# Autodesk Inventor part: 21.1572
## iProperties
Created: 2006-02
Part Number: 21.1572
Material: Steel, Mild
Description: M8 WASHER FOR LR6
Document SubType Name: Modeling
Standard: DIN 125
Designer: Andy Moles
Standards Organization: DIN
Language: en-US
Size Designation: A 8.4
Categories: <MemberInstance><Categories><Category DisplayName="Fasteners" InternalName="e4da775c-781d-43d5-af7c-5136215cf5a6" Mnemonic="FSTN"><Category DisplayName="Washers
Density: 7.86 g/cm^3
Author: Andy Moles
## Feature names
1. Body [Extrusion]
